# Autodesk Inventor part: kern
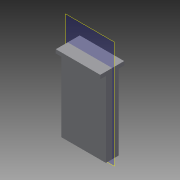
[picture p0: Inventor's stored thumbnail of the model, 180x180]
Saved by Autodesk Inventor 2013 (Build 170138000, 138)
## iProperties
Created: 2012-11
Part Number: kern
Material: Allgemein
Document SubType Name: Modeling
Designer: otto
Density: 1 g/cm^3
Mass: 8745.79 g
Surface Area: 3832.51 cm^2
Volume: 8745.79 cm^3
Author: otto
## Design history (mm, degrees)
sketch "Skizze1"
  geometry: L1 (119, -34)-(-119, -34) reference; L2 (119, 34)-(119, -34) reference; L3 (-119, 34)-(119, 34) reference; L4 (-119, -34)-(-119, 34) reference; 1 further point
extrude "Extrusion1" new body sketch "Skizze1" distance "d0" = 423; taper "d1" = 0 deg
sketch "Skizze4"
  geometry: L1 (238, 0)-(238, 423) reference; L2 (0, 0)-(0, 423) reference; L3 (284, 403)-(-21, 403) reference; L4 (0, 403)-(238, 403); L5 (238, 403)-(238, 423); L6 (238, 423)-(0, 423); L7 (0, 423)-(0, 403); 1 further point
  constraints: 8 end point, 3 point on line, 2 parallel, 1 horizontal, 1 perpendicular
  dimensions: "d13" = 20 distance of L5.end L4.end
extrude "Extrusion5" join sketch "Skizze4" distance "d14" = 30; taper "d15" = 0 deg
workplane "Arbeitsebene2"
mirror "Spiegeln2"
node "Volumenkörper1"
node "Referenz1"
node "Referenz3"
